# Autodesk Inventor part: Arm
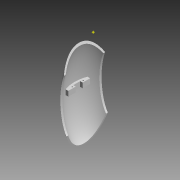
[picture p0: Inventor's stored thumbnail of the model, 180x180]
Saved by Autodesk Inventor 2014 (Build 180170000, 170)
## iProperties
Created: 2013-09
Part Number: Arm
Material: Generic
Document SubType Name: Modeling
Designer: Joey Mason
Appearance: Reflective - White
d70: 0.000 ul
d71: 90.0 deg
d72: 0.000 ul
d73: 90.0 deg
d74: 0.000 ul
d75: 90.0 deg
d76: 0.000 ul
d77: 90.0 deg
d78: 0.000 ul
d79: 90.0 deg
d80: 0.000 ul
d81: 90.0 deg
d82: 0.000 ul
d83: 90.0 deg
d85: 5.200 in
d119: 0.200 in
d121: 0.400 in
d123: 0.400 in
d124: 11.000 in
d125: 0.0 deg
d126: 0.300 in
d127: 11.000 in
d128: 0.0 deg
d129: 1.000 in
d130: 0.0 deg
d120: 90.0 deg
d122: 0.0 deg
d132: 0.834 in
d133: 1.100 in
d134: 0.0 deg
d143: 0.615 in
d144: 1.100 in
d145: 0.240 in
d146: 1.100 in
d147: 0.240 in
d148: 1.100 in
d149: 0.0 deg
d150: 0.300 in
d151: 0.0 deg
d152: 0.700 in
d153: 1.400 in
d154: 0.500 in
d155: 0.0 deg
Author: Joey Mason
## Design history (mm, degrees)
sketch "Sketch1"
  geometry: L1 (-962.26, 550.289)-(882.772, 550.289); L2 (882.772, 550.289)-(882.772, -680.347); L3 (882.772, -680.347)-(-962.26, -680.347); L4 (-962.26, -680.347)-(-962.26, 550.289); 4 further points; 1 other entity
  constraints: 1 vertical, 6 other
  node "Image1"
sketch "Sketch6"
  geometry: 5 further points; 1 other entity
  constraints: 1 coincident, 4 other
sketch "Sketch7"
  geometry: 4 further points; 1 other entity
  constraints: 1 coincident, 4 other
sketch "Sketch8"
  geometry: 4 further points; 1 other entity
  constraints: 4 other
sketch "Sketch9"
  geometry: 5 further points; 1 other entity
  constraints: 1 coincident, 2 other
workpoint "Work Point5"
loft "Loft2" dims count "d70" = 0, angle "d71" = 90 deg, count "d72" = 0, angle "d73" = 90 deg, count "d74" = 0, angle "d75" = 90 deg, count "d76" = 0, angle "d77" = 90 deg, count "d78" = 0, angle "d79" = 90 deg, count "d80" = 0, angle "d81" = 90 deg, count "d82" = 0, angle "d83" = 90 deg
workplane "Work Plane1"
sketch "Sketch10"
  geometry: L1 (0, 0)-(0.002, -165.1); L2 (-72.009, 197.105)-(-42.932, 117.215); L3 (-29.628, -144.286)-(-47.688, -246.71); L4 (-47.688, -246.71)-(-267.69, 18.133); L5 (-267.69, 18.133)-(-72.009, 197.105); L6 (267.69, 18.139)-(72.005, 197.107); L7 (72.005, 197.107)-(42.929, 117.216); L8 (47.694, -246.709)-(267.69, 18.139); L9 (29.631, -144.286)-(47.694, -246.709); L10 (-47.688, -246.71)-(-13.839, -360.721); L11 (-13.839, -360.721)-(47.694, -246.709); L12 (-72.009, 197.105)-(-64.474, 305.68); L13 (-64.474, 305.68)-(62.587, 305.681); L14 (62.587, 305.681)-(72.005, 197.107); 3 further points; 2 other entities
  constraints: 28 end point, 5 symmetric about line, 2 coincident, 12 other
sketch "Sketch14"
  geometry: L1 (-101.6, 0)-(-101.6, 5.08); L2 (-101.6, 0)-(-96.52, 0); L3 (-101.6, 5.08)-(-101.6, -5.08); L4 (-101.6, -5.08)-(-91.44, -5.08); L5 (-91.44, -5.08)-(-91.44, 5.08); L6 (-91.44, 5.08)-(-101.6, 5.08); 6 further points; 1 other entity
  constraints: 12 end point, 3 vertical, 2 horizontal, 2 perpendicular, 1 parallel, 2 other
  dimensions: "d119" = 5.08 distance of L1.start L1.end; "d120" = 90 deg angle of L2 L1 (derived); "d121" = 10.16 distance of L1.end L3.end; "d122" = 0 distance between parallel lines of L3 L1 (derived); "d123" = 10.16 distance of L3.end L4.end
extrude "Extrusion6" cut sketch "Sketch14" distance "d124" = 279.4; taper "d125" = 0 deg
shell "Shell2" dims "d126" = 7.62
extrude "Extrusion7" cut sketch "Sketch10" distance "d127" = 279.4; taper "d128" = 0 deg
sketch "Sketch15"
  geometry: L1 (0, 0)-(111.742, 0) reference; L2 (0, -25.4)-(111.742, -25.4) reference; 1 further point
  constraints: 2 vertical alignment
extrude "Extrusion8" join sketch "Sketch15" distance "d129" = 25.4; taper "d130" = 0 deg
sketch "Sketch18"
  geometry: L1 (0, 111.742)-(25.4, 111.742) reference; L2 (0, 111.742)-(21.184, 111.742); L3 (21.184, 112.379)-(26.007, 112.379); L4 (26.007, 112.379)-(26.007, -0.606); L5 (26.007, -0.606)-(21.184, -0.606); L6 (21.184, -0.606)-(21.184, 112.379); 1 further point
  constraints: 10 end point, 2 parallel, 1 horizontal, 1 perpendicular, 1 point on line
  dimensions: "d132" = 21.1836 distance of L1.start L2.end
extrude "Extrusion9" cut sketch "Sketch18" distance "d133" = 27.94; taper "d134" = 0 deg
sketch "Sketch20"
  geometry: L1 (0, 0)-(21.184, 0) reference; L2 (0, -111.742)-(21.184, -111.742) reference; L3 (21.184, -111.742)-(5.563, -111.742); L4 (5.563, -111.742)-(5.563, -83.802); L5 (5.563, 0)-(5.563, -27.94); C1 r 3.048 at (5.563, -83.802); C2 r 3.048 at (5.563, -27.94); 1 further point
  constraints: 6 end point, 2 centre point, 2 coincident, 2 point on line, 1 collinear, 1 perpendicular
  dimensions: "d143" = 15.621 distance of L2.end L3.end; "d144" = 27.94 distance of L3.end L4.end; "d145" = 6.096 diameter of C1; "d146" = 27.94 distance of L5.start L5.end; "d147" = 6.096 diameter of C2
extrude "Extrusion11" cut sketch "Sketch20" distance "d148" = 27.94; taper "d149" = 0 deg
sketch "Sketch21"
  geometry: L1 (111.742, -25.4)-(0, -25.4) reference; L2 (0, 0)-(111.742, 0) reference; 1 further point
  constraints: 2 vertical alignment
extrude "Extrusion12" cut sketch "Sketch21" distance "d150" = 7.62; taper "d151" = 0 deg
sketch "Sketch22"
  geometry: L1 (111.742, -25.4)-(0, -25.4) reference; L2 (0, 0)-(111.742, 0) reference; L3 (0, 0)-(55.871, 0); L4 (55.871, 0)-(38.091, 0); L5 (38.091, 0)-(73.651, 0); L6 (38.091, 0)-(73.651, 0); L7 (73.651, 0)-(73.651, -25.4); L8 (73.651, -25.4)-(38.091, -25.4); L9 (38.091, -25.4)-(38.091, 0); 1 further point
  constraints: 14 end point, 3 point on line, 2 parallel, 1 horizontal, 1 midpoint, 1 perpendicular
  dimensions: "d152" = 17.78 distance of L3.end L4.end; "d153" = 35.56 distance of L4.end L5.end
extrude "Extrusion13" cut sketch "Sketch22" distance "d154" = 12.7; taper "d155" = 0 deg
body "Solid2"
other parameters: "d85" = 132.08
